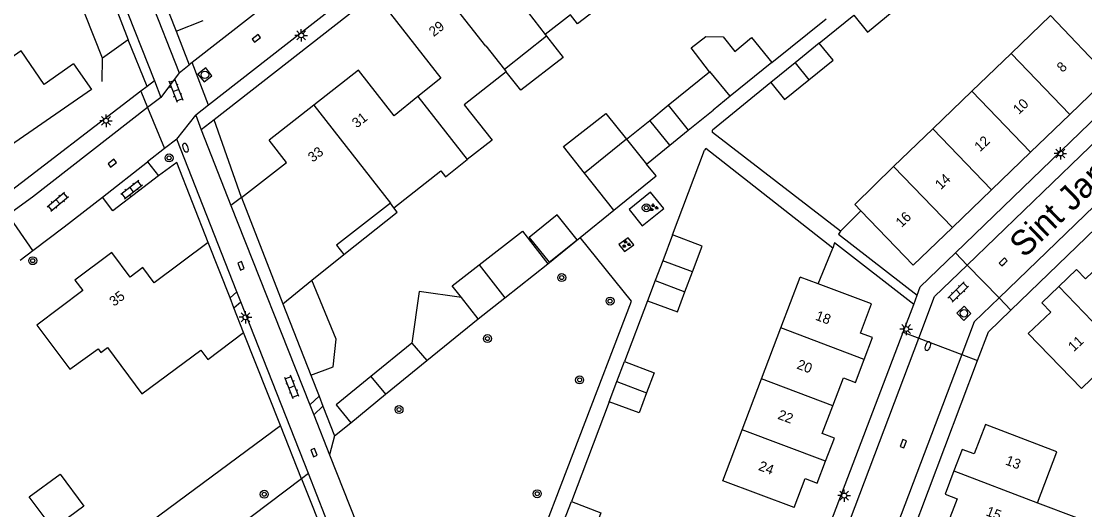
# Model space of a CAD drawing. Extents: x 136000 to 141014, y 402000 to 403500.
# Drawn here: x 137343.4 to 137450.2, y 402116.6 to 402165.7 of the extents above; entities that cross this region are included whole.
import ezdxf

# ---------------------------------------------------------------- set-up
doc = ezdxf.new("R2010")
doc.units = 0
for name, color, linetype in [('gg-afsc-erfafscheiding', 7, 'Continuous'), ('gg-afsc-hekwerk', 7, 'Continuous'), ('gg-afsc-muur', 7, 'Continuous'), ('gg-anno-huisnummerreeks BGT', 7, 'Continuous'), ('gg-anno-openbare ruimte label', 7, 'Continuous'), ('gg-bbg-bijgebouw', 7, 'Continuous'), ('gg-bbg-gedigitaliseerde bebouwing', 7, 'Continuous'), ('gg-bbg-gedigitaliseerde bijgebouw', 7, 'Continuous'), ('gg-bbg-hoofdgebouw', 7, 'Continuous'), ('gg-bbg-luifel en loopbrug', 7, 'Continuous'), ('gg-bbg-tussenscheiding', 7, 'Continuous'), ('gg-knt-verharding', 7, 'Continuous'), ('gg-knt-verharding nz', 7, 'Continuous'), ('gt-grn-groengrens', 7, 'Continuous'), ('gt-grn-weggrens', 7, 'Continuous'), ('gt-symb-boom', 7, 'Continuous'), ('gt-symb-brandkraan', 7, 'Continuous'), ('gt-symb-groenvak', 7, 'Continuous'), ('gt-symb-klinker verharding', 7, 'Continuous'), ('gt-symb-kolk', 7, 'Continuous'), ('gt-symb-lichtmast', 7, 'Continuous'), ('gt-symb-rioolschacht', 7, 'Continuous')]:
    doc.layers.add(name, color=color, linetype=linetype)

# ---------------------------------------------------------------- blocks, each defined once
blk = doc.blocks.new('gt0-KOLK')
at = {"layer": 'gt-symb-kolk'}
blk.add_lwpolyline([(0, 0), (0.38, 0), (0.38, 0.4), (-0.37, 0.4), (-0.37, 0), (0, 0)], dxfattribs=at)
blk = doc.blocks.new('gt0-LMAST')
at = {"layer": 'gt-symb-lichtmast'}
for p, q in [((-0.18, 0.17), (-0.45, 0.44)), ((0, 0.25), (0, 0.62)), ((0.17, 0.17), (0.44, 0.44)), ((-0.25, 0), (-0.63, 0)), ((-0.18, -0.18), (-0.45, -0.45)), ((0, -0.25), (0, -0.63)), ((0.44, -0.45), (0.17, -0.18)), ((0.25, 0), (0.62, 0))]:
    blk.add_line(p, q, dxfattribs=at)
blk.add_circle((0, 0), 0.25, dxfattribs=at)
blk = doc.blocks.new('gt0-BR')
at = {"layer": 'gt-symb-brandkraan'}
for centre, radius, start, end in [((-0.24, 0), 0.206, 107.5669, 252.4331), ((0.6, -2.66), 3, 106.892, 107.5669), ((0, -0.69), 0.938, 73.108, 106.892), ((-0.6, -2.66), 3, 72.4331, 73.108), ((0.24, 0), 0.206, 287.567, 72.4331), ((0.6, 2.66), 3, 252.4331, 253.108), ((0, 0.69), 0.938, 253.108, 286.8921), ((-0.6, 2.66), 3, 286.8921, 287.567)]:
    blk.add_arc(centre, radius, start, end, dxfattribs=at)
blk = doc.blocks.new('gt0-RS')
at = {"layer": 'gt-symb-rioolschacht'}
blk.add_lwpolyline([(-0.5, -0.5), (0.5, -0.5), (0.5, 0.5), (-0.5, 0.5)], close=True, dxfattribs=at)
blk.add_circle((0, 0), 0.375, dxfattribs=at)
blk = doc.blocks.new('gt0-KL1')
at = {"layer": 'gt-symb-klinker verharding'}
for p, q in [((-1.15, 0.3), (1.15, 0.3)), ((-1, -0.3), (-1, 0.3)), ((-0.5, 0.3), (-0.5, 0.45)), ((0, -0.3), (0, 0.3)), ((0.5, 0.3), (0.5, 0.45)), ((1, -0.3), (1, 0.3)), ((-1.15, -0.3), (1.15, -0.3)), ((-0.5, -0.45), (-0.5, -0.3)), ((0.5, -0.45), (0.5, -0.3))]:
    blk.add_line(p, q, dxfattribs=at)
blk = doc.blocks.new('gt0-BOOM')
at = {"layer": 'gt-symb-boom'}
for radius in [0.4, 0.2]:
    blk.add_circle((0, 0), radius, dxfattribs=at)
blk = doc.blocks.new('gt0-GRVAK')
at = {"layer": 'gt-symb-groenvak'}
for p, q in [((-0.11, 0.19), (-0.23, 0.24)), ((-0.18, 0.15), (0.09, 0.15)), ((-0.09, 0.21), (-0.16, 0.32)), ((-0.05, 0.21), (-0.05, 0.39)), ((0, 0.21), (0.06, 0.32)), ((0.02, 0.19), (0.13, 0.24)), ((0.26, -0.05), (0.2, 0.06)), ((0.31, -0.05), (0.31, 0.13)), ((0.35, -0.05), (0.41, 0.06)), ((-0.24, -0.23), (-0.36, -0.18)), ((-0.32, -0.26), (-0.05, -0.26)), ((-0.23, -0.21), (-0.29, -0.1)), ((-0.18, -0.2), (-0.18, -0.02)), ((-0.14, -0.21), (-0.07, -0.1)), ((-0.12, -0.23), (0, -0.18)), ((0.24, -0.07), (0.12, -0.02)), ((0.17, -0.11), (0.44, -0.11)), ((0.37, -0.07), (0.49, -0.02))]:
    blk.add_line(p, q, dxfattribs=at)

msp = doc.modelspace()

# ---------------------------------------------------------------- linework, layer by layer
at = {"layer": 'gg-afsc-erfafscheiding'}
for p, q in [((137423.52, 402163.5), (137426.98, 402166.31)), ((137418.75, 402161.55), (137424.19, 402165.94)), ((137358.95, 402164.71), (137360.27, 402161.33)), ((137356.04, 402159.14), (137354.16, 402163.82)), ((137418.64, 402159.53), (137412.79, 402154.77)), ((137365.52, 402147.98), (137362.77, 402155.8)), ((137408.77, 402144.24), (137411.98, 402152.76)), ((137425.63, 402144.59), (137427.69, 402146.65)), ((137423.39, 402139.32), (137424.86, 402142.91)), ((137406.28, 402137.61), (137403.96, 402131.5)), ((137402.43, 402127.46), (137398.63, 402117.44)), ((137334.59, 402099.31), (137369.43, 402125.08))]:
    msp.add_line(p, q, dxfattribs=at)
for points in [[(137425.63, 402144.59), (137412.81, 402154.52), (137412.79, 402154.77)], [(137424.86, 402142.91), (137412.14, 402152.91), (137411.98, 402152.76)], [(137362.19, 402143.48), (137359.02, 402151.52), (137357.2, 402150.15)]]:
    msp.add_lwpolyline(points, dxfattribs=at)
at = {"layer": 'gg-afsc-hekwerk'}
msp.add_line((137374.87, 402124.03), (137374.36, 402122.14), dxfattribs=at)
for points in [[(137388.12, 402103.54), (137389.58, 402104.86), (137391.85, 402111.01), (137394.17, 402110.11), (137404.65, 402137.58), (137399.51, 402143.97)], [(137374.36, 402122.14), (137377.1, 402115.19), (137379.75, 402112.39)]]:
    msp.add_lwpolyline(points, dxfattribs=at)
at = {"layer": 'gg-afsc-muur'}
for p, q in [((137351.55, 402159.66), (137351.56, 402162)), ((137399.51, 402143.97), (137402.88, 402146.73)), ((137396.27, 402141.33), (137399.51, 402143.97)), ((137369.43, 402125.08), (137365.73, 402134.42)), ((137372.47, 402130.15), (137373.31, 402128.01)), ((137373.31, 402128.01), (137373.7, 402127.01)), ((137373.7, 402127.01), (137374.87, 402124.03)), ((137374.87, 402124.03), (137376.5, 402125.36))]:
    msp.add_line(p, q, dxfattribs=at)
at = {"layer": 'gg-bbg-bijgebouw'}
for p, q in [((137351.58, 402170.48), (137354.16, 402163.82)), ((137356.41, 402171.2), (137358.95, 402164.71)), ((137358.95, 402164.71), (137361.67, 402165.76)), ((137354.16, 402163.82), (137351.56, 402162)), ((137402.88, 402146.73), (137407.14, 402150.18)), ((137407.8, 402141.63), (137407.05, 402139.64)), ((137410.03, 402138.51), (137410.78, 402140.51)), ((137407.05, 402139.64), (137406.28, 402137.61)), ((137403.2, 402129.5), (137403.96, 402131.5)), ((137402.43, 402127.46), (137403.2, 402129.5)), ((137397.86, 402115.45), (137398.63, 402117.44))]:
    msp.add_line(p, q, dxfattribs=at)
for points in [[(137351.56, 402162), (137348.94, 402168.68), (137351.58, 402170.48)], [(137406.28, 402137.61), (137409.27, 402136.49), (137410.03, 402138.51)], [(137403.96, 402131.5), (137406.94, 402130.37), (137406.18, 402128.37)], [(137406.18, 402128.37), (137405.42, 402126.34), (137402.43, 402127.46)], [(137344.21, 402117.9), (137347.32, 402120.18), (137349.69, 402116.97), (137346.6, 402114.68), (137344.21, 402117.9)], [(137398.63, 402117.44), (137401.6, 402116.29), (137400.84, 402114.3)]]:
    msp.add_lwpolyline(points, dxfattribs=at)
at = {"layer": 'gg-bbg-gedigitaliseerde bebouwing'}
for p, q in [((137396.14, 402164.2), (137391.93, 402160.85)), ((137396.01, 402164.36), (137396.14, 402164.2)), ((137442.76, 402162.47), (137438.83, 402158.68)), ((137391.93, 402160.85), (137392.1, 402160.63)), ((137438.83, 402158.68), (137434.9, 402154.9)), ((137434.9, 402154.9), (137430.97, 402151.11)), ((137430.97, 402151.11), (137427.08, 402147.29)), ((137380.81, 402146.96), (137380.46, 402147.41)), ((137372.58, 402139.67), (137375.78, 402142.27)), ((137369.67, 402137.3), (137372.58, 402139.67)), ((137419.67, 402134.88), (137421.61, 402139.99)), ((137417.72, 402129.76), (137419.67, 402134.88)), ((137415.78, 402124.65), (137417.72, 402129.76)), ((137413.85, 402119.51), (137415.78, 402124.65))]:
    msp.add_line(p, q, dxfattribs=at)
for points in [[(137400.79, 402166.94), (137400.95, 402166.73), (137399.26, 402165.43), (137398.56, 402166.34), (137396.01, 402164.36)], [(137452.59, 402160.13), (137446.71, 402166.28), (137442.76, 402162.47)], [(137348.67, 402161.41), (137345.7, 402159.36), (137343.39, 402162.71), (137335.96, 402157.54)], [(137392.1, 402160.63), (137387.88, 402157.31), (137390.67, 402153.76), (137388.17, 402151.8)], [(137380.81, 402146.96), (137385.52, 402150.68), (137385.99, 402150.08), (137388.17, 402151.8)], [(137380.46, 402147.41), (137375.05, 402143.2), (137375.78, 402142.27)], [(137444.49, 402134.33), (137449.85, 402128.8), (137453.76, 402132.57)], [(137445.42, 402117.31), (137447.37, 402122.42), (137440.2, 402125.17)], [(137445.42, 402117.31), (137449.32, 402115.82), (137447.36, 402110.7), (137443.46, 402112.19)]]:
    msp.add_lwpolyline(points, dxfattribs=at)
at = {"layer": 'gg-bbg-gedigitaliseerde bijgebouw'}
for p, q in [((137423.52, 402163.5), (137421.08, 402161.52)), ((137418.75, 402161.55), (137414.57, 402158.16)), ((137421.08, 402161.52), (137418.64, 402159.53)), ((137408.35, 402157.25), (137412.49, 402160.61)), ((137414.57, 402158.16), (137412.85, 402156.76)), ((137406.49, 402155.73), (137408.35, 402157.25)), ((137410.37, 402154.75), (137412.85, 402156.76)), ((137408.51, 402153.24), (137406.49, 402155.73)), ((137408.51, 402153.24), (137410.37, 402154.75)), ((137404.17, 402153.85), (137399.96, 402150.44)), ((137404.17, 402153.85), (137406.18, 402151.35)), ((137407.14, 402150.18), (137406.18, 402151.35)), ((137402.88, 402146.73), (137399.96, 402150.44)), ((137408.77, 402144.24), (137407.8, 402141.63)), ((137389.36, 402141.21), (137391.94, 402137.9)), ((137389.27, 402135.79), (137387.6, 402137.93)), ((137389.27, 402135.79), (137391.94, 402137.9)), ((137382.61, 402133.36), (137378.51, 402130.01)), ((137382.61, 402133.36), (137384.13, 402131.6)), ((137379.99, 402128.21), (137384.13, 402131.6)), ((137378.51, 402130.01), (137379.99, 402128.21))]:
    msp.add_line(p, q, dxfattribs=at)
for points in [[(137426.98, 402166.31), (137428.37, 402164.61), (137430.84, 402166.63), (137429.46, 402168.33)], [(137412.49, 402160.61), (137410.64, 402163.02), (137412.12, 402164.16), (137413.88, 402164.14), (137415.03, 402162.67)], [(137415.03, 402162.67), (137416.72, 402164.05), (137418.75, 402161.55)], [(137422.47, 402159.81), (137424.91, 402161.79), (137423.52, 402163.5)], [(137418.64, 402159.53), (137420.03, 402157.82), (137422.47, 402159.81)], [(137394.38, 402143.97), (137396.39, 402141.48), (137399.21, 402143.75), (137397.2, 402146.24), (137394.38, 402143.97)], [(137410.78, 402140.51), (137411.76, 402143.11), (137408.77, 402144.24)], [(137387.6, 402137.93), (137386.68, 402139.12), (137389.36, 402141.21)]]:
    msp.add_lwpolyline(points, dxfattribs=at)
at = {"layer": 'gg-bbg-hoofdgebouw'}
for p, q in [((137448.66, 402156.34), (137452.59, 402160.13)), ((137372.78, 402157.27), (137368.28, 402153.76)), ((137444.73, 402152.56), (137448.66, 402156.34)), ((137440.81, 402148.77), (137444.73, 402152.56)), ((137365.52, 402147.98), (137369.67, 402137.3)), ((137436.88, 402144.99), (137440.81, 402148.77)), ((137427.69, 402146.65), (137427.08, 402147.29)), ((137432.95, 402141.2), (137427.69, 402146.65)), ((137432.95, 402141.2), (137436.88, 402144.99)), ((137364.37, 402137.9), (137362.19, 402143.48)), ((137423.39, 402139.32), (137421.61, 402139.99)), ((137428.74, 402137.3), (137423.39, 402139.32)), ((137364.76, 402136.91), (137364.37, 402137.9)), ((137365.73, 402134.42), (137364.76, 402136.91)), ((137420.98, 402116.82), (137413.85, 402119.51))]:
    msp.add_line(p, q, dxfattribs=at)
for points in [[(137381.52, 402167.24), (137380.48, 402166.43), (137385.52, 402159.97), (137383.23, 402158.13)], [(137348.67, 402161.41), (137350.45, 402158.84), (137340.04, 402151.64), (137335.96, 402157.54)], [(137383.23, 402158.13), (137380.83, 402156.21), (137377.28, 402160.78), (137372.78, 402157.27)], [(137365.52, 402147.98), (137370.04, 402151.49), (137368.28, 402153.76)], [(137362.19, 402143.48), (137356.74, 402139.42), (137355.62, 402140.96), (137354.33, 402139.98), (137352.49, 402142.46), (137348.79, 402139.68), (137349.58, 402138.65), (137344.97, 402135.17)], [(137452.41, 402141.89), (137450.25, 402139.81), (137449.35, 402140.75), (137447.56, 402139.03)], [(137447.56, 402139.03), (137445.87, 402137.4), (137446.77, 402136.46), (137444.49, 402134.33)], [(137428.02, 402131.72), (137428.86, 402133.92), (137427.64, 402134.35), (137428.74, 402137.3)], [(137344.97, 402135.17), (137348.28, 402130.75), (137351.12, 402132.79), (137351.4, 402132.42), (137352.07, 402132.93), (137355.52, 402128.26), (137361.43, 402132.66), (137362.14, 402131.71), (137365.73, 402134.42)], [(137424.87, 402127.06), (137425.93, 402129.87), (137427.14, 402129.41), (137428.02, 402131.72)], [(137424.14, 402121.48), (137425.03, 402123.81), (137423.81, 402124.27), (137424.87, 402127.06)], [(137440.2, 402125.17), (137439.07, 402122.22), (137437.85, 402122.66), (137437.03, 402120.51)], [(137420.98, 402116.82), (137422.11, 402119.76), (137423.3, 402119.29), (137424.14, 402121.48)], [(137437.03, 402120.51), (137436.14, 402118.19), (137437.35, 402117.72), (137436.29, 402114.93)]]:
    msp.add_lwpolyline(points, dxfattribs=at)
at = {"layer": 'gg-bbg-luifel en loopbrug'}
for p, q in [((137404.17, 402153.85), (137406.49, 402155.73)), ((137406.18, 402151.35), (137408.51, 402153.24)), ((137381.16, 402146.51), (137380.81, 402146.96)), ((137375.78, 402142.27), (137381.16, 402146.51)), ((137391.94, 402137.9), (137396.27, 402141.33)), ((137369.67, 402137.3), (137372.47, 402130.15)), ((137384.13, 402131.6), (137389.27, 402135.79)), ((137376.5, 402125.36), (137379.99, 402128.21))]:
    msp.add_line(p, q, dxfattribs=at)
for points in [[(137396.14, 402164.2), (137397.8, 402162.07), (137393.56, 402158.76), (137392.1, 402160.63)], [(137399.96, 402150.44), (137397.85, 402153.12), (137402.09, 402156.44), (137404.17, 402153.85)], [(137389.36, 402141.21), (137393.71, 402144.61), (137396.27, 402141.33)], [(137372.47, 402130.15), (137374.71, 402130.98), (137375.02, 402133.76), (137372.58, 402139.67)], [(137387.6, 402137.93), (137383.35, 402138.54), (137382.61, 402133.36)], [(137378.51, 402130.01), (137375.03, 402127.17), (137376.5, 402125.36)]]:
    msp.add_lwpolyline(points, dxfattribs=at)
at = {"layer": 'gg-bbg-tussenscheiding'}
for p, q in [((137448.66, 402156.34), (137442.76, 402162.47)), ((137421.08, 402161.52), (137422.47, 402159.81)), ((137444.73, 402152.56), (137438.83, 402158.68)), ((137383.23, 402158.13), (137388.17, 402151.8)), ((137372.78, 402157.27), (137380.46, 402147.41)), ((137408.35, 402157.25), (137410.37, 402154.75)), ((137440.81, 402148.77), (137434.9, 402154.9)), ((137436.88, 402144.99), (137430.97, 402151.11)), ((137410.78, 402140.51), (137407.8, 402141.63)), ((137407.05, 402139.64), (137410.03, 402138.51)), ((137447.56, 402139.03), (137453.76, 402132.57)), ((137428.02, 402131.72), (137419.67, 402134.88)), ((137424.87, 402127.06), (137417.72, 402129.76)), ((137403.2, 402129.5), (137406.18, 402128.37)), ((137424.14, 402121.48), (137415.78, 402124.65)), ((137437.03, 402120.51), (137445.42, 402117.31))]:
    msp.add_line(p, q, dxfattribs=at)
for points in [[(137389.23, 402173.26), (137389.17, 402173.21), (137394.23, 402166.54), (137394.28, 402166.58), (137396.01, 402164.36)], [(137384.84, 402169.83), (137390, 402163.18), (137390.06, 402163.22), (137391.93, 402160.85)], [(137414.57, 402158.16), (137412.54, 402160.65), (137412.49, 402160.61)]]:
    msp.add_lwpolyline(points, dxfattribs=at)
at = {"layer": 'gg-knt-verharding'}
for p, q in [((137346.44, 402186.13), (137356.77, 402159.7)), ((137390.24, 402179.17), (137362.21, 402157.28)), ((137437.19, 402142.42), (137471.64, 402175.76)), ((137385.63, 402173.68), (137362.77, 402155.8)), ((137354.86, 402171.73), (137359.25, 402160.53)), ((137359.25, 402160.53), (137360.27, 402161.33)), ((137360.57, 402161.56), (137360.27, 402161.33)), ((137362.21, 402157.28), (137360.57, 402161.56)), ((137356.77, 402159.7), (137356.04, 402159.14)), ((137355.42, 402158.67), (137341.1, 402147.69)), ((137356.04, 402159.14), (137355.42, 402158.67)), ((137355.42, 402158.67), (137356.1, 402157.02)), ((137356.1, 402157.02), (137357.8, 402152.9)), ((137362.21, 402157.28), (137360.92, 402156.27)), ((137360.92, 402156.27), (137361.46, 402154.78)), ((137362.77, 402155.8), (137361.46, 402154.78)), ((137361.46, 402154.78), (137364.46, 402147.19)), ((137359.02, 402153.85), (137357.8, 402152.9)), ((137365.06, 402138.5), (137359.02, 402153.85)), ((137357.8, 402152.9), (137356.1, 402151.57)), ((137351.56, 402148.03), (137356.1, 402151.57)), ((137356.1, 402151.57), (137357.2, 402150.15)), ((137364.46, 402147.19), (137372.38, 402127.15)), ((137344.56, 402142.66), (137342.1, 402146.24)), ((137343.3, 402141.69), (137344.56, 402142.66)), ((137438.36, 402141.2), (137437.19, 402142.42)), ((137441.56, 402137.9), (137438.36, 402141.2)), ((137365.45, 402137.51), (137365.06, 402138.5)), ((137372.23, 402120.25), (137365.45, 402137.51)), ((137431.92, 402134.44), (137432.99, 402137.25)), ((137432.99, 402137.25), (137433.33, 402138.16)), ((137442.74, 402136.68), (137441.56, 402137.9)), ((137431.92, 402134.44), (137433.5, 402133.84)), ((137433.5, 402133.84), (137437.82, 402132.21)), ((137437.82, 402132.21), (137439.4, 402131.61)), ((137428.61, 402103.06), (137439.4, 402131.61)), ((137372.38, 402127.15), (137372.77, 402126.16)), ((137372.77, 402126.16), (137374.36, 402122.14))]:
    msp.add_line(p, q, dxfattribs=at)
for points in [[(137442.74, 402136.68), (137492.98, 402185.2), (137496.05, 402185.43)], [(137384.99, 402180.89), (137385.08, 402180.71), (137360.57, 402161.56)], [(137357.2, 402150.15), (137352.62, 402146.65), (137351.56, 402148.03)], [(137344.56, 402142.66), (137347.73, 402145.04), (137351.56, 402148.03)], [(137404.43, 402146.78), (137405.75, 402145.14), (137407.91, 402146.88), (137406.58, 402148.52), (137404.43, 402146.78)], [(137403.4, 402143.25), (137403.96, 402142.56), (137404.9, 402143.23), (137404.34, 402143.92), (137403.4, 402143.25)], [(137425.63, 402144.59), (137425.44, 402144.32), (137433.33, 402138.16)], [(137432.99, 402137.25), (137425.05, 402143.43), (137424.86, 402142.91)], [(137433.33, 402138.16), (137433.65, 402139), (137437.19, 402142.42)], [(137439.4, 402131.61), (137440.49, 402134.5), (137442.74, 402136.68)], [(137414.48, 402088.37), (137416.88, 402094.86), (137431.92, 402134.44)], [(137377.95, 402110.43), (137374.76, 402113.82), (137372.23, 402120.25)]]:
    msp.add_lwpolyline(points, dxfattribs=at)
at = {"layer": 'gg-knt-verharding nz'}
for p, q in [((137438.36, 402141.2), (137472.92, 402174.59)), ((137356.77, 402159.7), (137357.41, 402158.04)), ((137357.41, 402158.04), (137356.1, 402157.02)), ((137416.09, 402087.76), (137433.5, 402133.84)), ((137437.82, 402132.21), (137420.53, 402086.47))]:
    msp.add_line(p, q, dxfattribs=at)
for points in [[(137494.32, 402187.02), (137492.18, 402186.85), (137441.56, 402137.9)], [(137356.1, 402157.02), (137344.54, 402148.03), (137342.1, 402146.24)], [(137433.5, 402133.84), (137435.08, 402138.03), (137438.36, 402141.2)], [(137441.56, 402137.9), (137439.06, 402135.48), (137437.82, 402132.21)]]:
    msp.add_lwpolyline(points, dxfattribs=at)
at = {"layer": 'gt-grn-groengrens'}
for p, q in [((137365.52, 402147.98), (137364.46, 402147.19)), ((137365.06, 402138.5), (137364.37, 402137.9)), ((137364.76, 402136.91), (137365.45, 402137.51)), ((137373.31, 402128.01), (137372.38, 402127.15)), ((137372.77, 402126.16), (137373.7, 402127.01)), ((137371.55, 402119.73), (137369.43, 402125.08)), ((137372.23, 402120.25), (137371.55, 402119.73))]:
    msp.add_line(p, q, dxfattribs=at)
for points in [[(137371.55, 402119.73), (137355.03, 402107.22), (137367.46, 402091.38), (137359.15, 402084.97), (137355.5, 402089.05)], [(137371.55, 402119.73), (137374.13, 402113.24), (137375.06, 402108.4), (137377.35, 402109.97), (137377.95, 402110.43)]]:
    msp.add_lwpolyline(points, dxfattribs=at)
at = {"layer": 'gt-grn-weggrens'}
for p, q in [((137359.25, 402160.53), (137357.41, 402158.04)), ((137359.02, 402153.85), (137360.92, 402156.27))]:
    msp.add_line(p, q, dxfattribs=at)

# ---------------------------------------------------------------- block references
at = {"layer": 'gt-symb-boom'}
for p in [(137358.25, 402151.96), (137406.15, 402146.95), (137344.56, 402141.64), (137397.66, 402139.94), (137402.51, 402137.58), (137390.21, 402133.81), (137399.46, 402129.66), (137381.33, 402126.68), (137367.8, 402118.17), (137395.2, 402118.22)]:
    msp.add_blockref('gt0-BOOM', p, dxfattribs=at)
at = {"layer": 'gt-symb-brandkraan'}
for p, rotation in [((137359.9, 402152.99), -68.53893641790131), ((137434.41, 402133.05), -110.48229688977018)]:
    msp.add_blockref('gt0-BR', p, dxfattribs=dict(at, rotation=rotation))
at = {"layer": 'gt-symb-groenvak'}
for p in [(137406.89, 402146.98), (137404.12, 402143.3)]:
    msp.add_blockref('gt0-GRVAK', p, dxfattribs=at)
at = {"layer": 'gt-symb-klinker verharding'}
for p, rotation in [((137358.92, 402158.74), -68.59226005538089), ((137354.49, 402148.78), 37.64891642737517), ((137347.08, 402147.57), 40.0109577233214), ((137437.46, 402138.48), 44.67584063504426), ((137370.57, 402128.94), 111.28016631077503)]:
    msp.add_blockref('gt0-KL1', p, dxfattribs=dict(at, rotation=rotation))
at = {"layer": 'gt-symb-kolk'}
for p, rotation in [((137367.13, 402163.82), 38.01566048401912), ((137352.66, 402151.28), 38.01566048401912), ((137365.27, 402141.05), -68.59226005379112), ((137442.1, 402141.37), 43.946589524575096), ((137432.13, 402123.18), 69.33669709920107), ((137372.6, 402122.29), -68.59226005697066)]:
    msp.add_blockref('gt0-KOLK', p, dxfattribs=dict(at, rotation=rotation))
at = {"layer": 'gt-symb-lichtmast'}
for p in [(137371.51, 402164.28), (137351.92, 402155.7), (137447.72, 402152.42), (137365.92, 402135.95), (137432.24, 402134.77), (137426.02, 402118.03)]:
    msp.add_blockref('gt0-LMAST', p, dxfattribs=at)
at = {"layer": 'gt-symb-rioolschacht'}
for p, rotation in [((137361.85, 402160.31), 38.01566048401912), ((137438.03, 402136.35), 43.94658952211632)]:
    msp.add_blockref('gt0-RS', p, dxfattribs=dict(at, rotation=rotation))

# ---------------------------------------------------------------- texts
at = {"layer": 'gg-anno-huisnummerreeks BGT'}
for s, rotation, p in [('29', 37.9, (137384.81, 402164.1)), ('8', 43.9, (137447.93, 402160.5)), ('10', 43.9, (137443.54, 402156.27)), ('31', 38, (137377.09, 402154.92)), ('12', 43.9, (137439.66, 402152.53)), ('33', 37.9, (137372.67, 402151.48)), ('14', 43.9, (137435.71, 402148.72)), ('16', 43.9, (137431.76, 402144.91)), ('35', 37, (137352.72, 402137)), ('18', 339.6, (137423.05, 402135.72)), ('11', 43.1, (137449.06, 402132.44)), ('20', 339.3, (137421.18, 402130.82)), ('22', 339.3, (137419.27, 402125.77)), ('24', 339, (137417.33, 402120.63)), ('13', 339, (137442.12, 402121.18)), ('15', 339.2, (137440.17, 402116.06))]:
    msp.add_text(s, height=1, rotation=rotation, dxfattribs=at).set_placement(p)
at = {"layer": 'gg-anno-openbare ruimte label'}
msp.add_text('Sint Janskruid', height=2.5, rotation=44, dxfattribs=at).set_placement((137444.09, 402141.84))

doc.saveas('drawing.dxf')
